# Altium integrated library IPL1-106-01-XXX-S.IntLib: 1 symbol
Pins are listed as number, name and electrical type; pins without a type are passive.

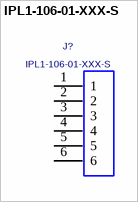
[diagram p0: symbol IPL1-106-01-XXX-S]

## IPL1-106-01-XXX-S
designator J?
0.1 INCH SINGLE ROW TERMINAL ASSEMBLY, 6 PINS.; MANUFACTURER: SAMTEC
footprint IPL1-106-01-XXX-S
pins: 1, 2, 3, 4, 5, 6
